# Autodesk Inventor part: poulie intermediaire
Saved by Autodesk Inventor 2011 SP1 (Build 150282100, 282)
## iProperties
Created: 2010-12
Part Number: poulie intermediaire
Document SubType Name: Modeling
Designer: eric
Density: 1 g/cm^3
Mass: 80.9676 g
Surface Area: 663.515 cm^2
Volume: 80.9676 cm^3
Author: eric
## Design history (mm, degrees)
feature "Base1"
node "Solide1"
node "Corps solides"
node "Corps surfaciques"
